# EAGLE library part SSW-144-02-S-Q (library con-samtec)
THROUGH-HOLE .025" SQ POST SOCKET Source: Samtec SSW.pdf
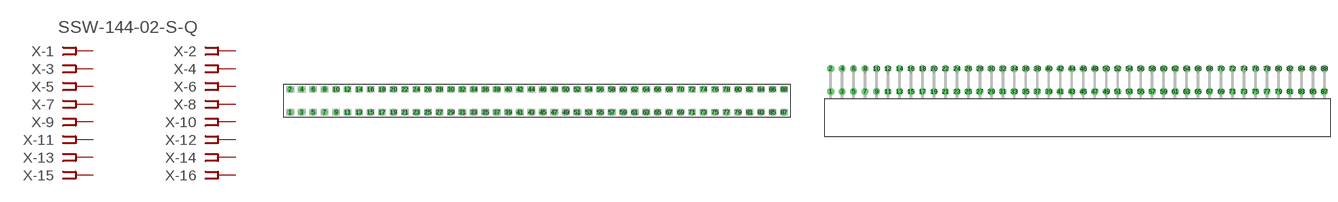
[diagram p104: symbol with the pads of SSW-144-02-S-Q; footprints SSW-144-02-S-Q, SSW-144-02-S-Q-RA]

Designator prefix X; gates -1=FPINV -2=FPIN -3=FPIN -4=FPIN -5=FPIN -6=FPIN -7=FPIN -8=FPIN -9=FPIN -10=FPIN -11=FPIN -12=FPIN -13=FPIN -14=FPIN -15=FPIN -16=FPIN -17=FPIN -18=FPIN -19=FPIN -20=FPIN -21=FPIN -22=FPIN -23=FPIN -24=FPIN -25=FPIN -26=FPIN -27=FPIN -28=FPIN -29=FPIN -30=FPIN -31=FPIN -32=FPIN -33=FPIN -34=FPIN -35=FPIN -36=FPIN -37=FPIN -38=FPIN -39=FPIN -40=FPIN -41=FPIN -42=FPIN -43=FPIN -44=FPIN -45=FPIN -46=FPIN -47=FPIN -48=FPIN -49=FPIN -50=FPIN -51=FPIN -52=FPIN -53=FPIN -54=FPIN -55=FPIN -56=FPIN -57=FPIN -58=FPIN -59=FPIN -60=FPIN -61=FPIN -62=FPIN -63=FPIN -64=FPIN -65=FPIN -66=FPIN -67=FPIN -68=FPIN -69=FPIN -70=FPIN -71=FPIN -72=FPIN -73=FPIN -74=FPIN -75=FPIN -76=FPIN -77=FPIN -78=FPIN -79=FPIN -80=FPIN -81=FPIN -82=FPIN -83=FPIN -84=FPIN -85=FPIN -86=FPIN -87=FPIN -88=FPIN

## SSW-144-02-S-Q (OC_FARNELL: unknown; OC_NEWARK: unknown)  [SSW-144-02-S-Q]
1  -1:1  pas
2  -2:1  pas
3  -3:1  pas
4  -4:1  pas
5  -5:1  pas
6  -6:1  pas
7  -7:1  pas
8  -8:1  pas
9  -9:1  pas
10  -10:1  pas
11  -11:1  pas
12  -12:1  pas
13  -13:1  pas
14  -14:1  pas
15  -15:1  pas
16  -16:1  pas
17  -17:1  pas
18  -18:1  pas
19  -19:1  pas
20  -20:1  pas
21  -21:1  pas
22  -22:1  pas
23  -23:1  pas
24  -24:1  pas
25  -25:1  pas
26  -26:1  pas
27  -27:1  pas
28  -28:1  pas
29  -29:1  pas
30  -30:1  pas
31  -31:1  pas
32  -32:1  pas
33  -33:1  pas
34  -34:1  pas
35  -35:1  pas
36  -36:1  pas
37  -37:1  pas
38  -38:1  pas
39  -39:1  pas
40  -40:1  pas
41  -41:1  pas
42  -42:1  pas
43  -43:1  pas
44  -44:1  pas
45  -45:1  pas
46  -46:1  pas
47  -47:1  pas
48  -48:1  pas
49  -49:1  pas
50  -50:1  pas
51  -51:1  pas
52  -52:1  pas
53  -53:1  pas
54  -54:1  pas
55  -55:1  pas
56  -56:1  pas
57  -57:1  pas
58  -58:1  pas
59  -59:1  pas
60  -60:1  pas
61  -61:1  pas
62  -62:1  pas
63  -63:1  pas
64  -64:1  pas
65  -65:1  pas
66  -66:1  pas
67  -67:1  pas
68  -68:1  pas
69  -69:1  pas
70  -70:1  pas
71  -71:1  pas
72  -72:1  pas
73  -73:1  pas
74  -74:1  pas
75  -75:1  pas
76  -76:1  pas
77  -77:1  pas
78  -78:1  pas
79  -79:1  pas
80  -80:1  pas
81  -81:1  pas
82  -82:1  pas
83  -83:1  pas
84  -84:1  pas
85  -85:1  pas
86  -86:1  pas
87  -87:1  pas
88  -88:1  pas

## SSW-144-02-S-QRA (OC_FARNELL: unknown; OC_NEWARK: unknown)  [SSW-144-02-S-Q-RA]
Pads as for SSW-144-02-S-Q

## Footprint SSW-144-02-S-Q (pad centres in mm)
THROUGH-HOLE .025" SQ POST SOCKET Source: Samtec SSW.pdf
drill 1 pad 1.5 octagon: 1 -54.61,-2.54; 2 -54.61,2.54; 3 -52.07,-2.54; 4 -52.07,2.54; 5 -49.53,-2.54; 6 -49.53,2.54; 7 -46.99,-2.54; 8 -46.99,2.54; 9 -44.45,-2.54; 10 -44.45,2.54; 11 -41.91,-2.54; 12 -41.91,2.54; 13 -39.37,-2.54; 14 -39.37,2.54; 15 -36.83,-2.54; 16 -36.83,2.54; 17 -34.29,-2.54; 18 -34.29,2.54; 19 -31.75,-2.54; 20 -31.75,2.54; 21 -29.21,-2.54; 22 -29.21,2.54; 23 -26.67,-2.54; 24 -26.67,2.54; 25 -24.13,-2.54; 26 -24.13,2.54; 27 -21.59,-2.54; 28 -21.59,2.54; 29 -19.05,-2.54; 30 -19.05,2.54; 31 -16.51,-2.54; 32 -16.51,2.54; 33 -13.97,-2.54; 34 -13.97,2.54; 35 -11.43,-2.54; 36 -11.43,2.54; 37 -8.89,-2.54; 38 -8.89,2.54; 39 -6.35,-2.54; 40 -6.35,2.54; 41 -3.81,-2.54; 42 -3.81,2.54; 43 -1.27,-2.54; 44 -1.27,2.54; 45 1.27,-2.54; 46 1.27,2.54; 47 3.81,-2.54; 48 3.81,2.54; 49 6.35,-2.54; 50 6.35,2.54; 51 8.89,-2.54; 52 8.89,2.54; 53 11.43,-2.54; 54 11.43,2.54; 55 13.97,-2.54; 56 13.97,2.54; 57 16.51,-2.54; 58 16.51,2.54; 59 19.05,-2.54; 60 19.05,2.54; 61 21.59,-2.54; 62 21.59,2.54; 63 24.13,-2.54; 64 24.13,2.54; 65 26.67,-2.54; 66 26.67,2.54; 67 29.21,-2.54; 68 29.21,2.54; 69 31.75,-2.54; 70 31.75,2.54; 71 34.29,-2.54; 72 34.29,2.54; 73 36.83,-2.54; 74 36.83,2.54; 75 39.37,-2.54; 76 39.37,2.54; 77 41.91,-2.54; 78 41.91,2.54; 79 44.45,-2.54; 80 44.45,2.54; 81 46.99,-2.54; 82 46.99,2.54; 83 49.53,-2.54; 84 49.53,2.54; 85 52.07,-2.54; 86 52.07,2.54; 87 54.61,-2.54; 88 54.61,2.54

## Footprint SSW-144-02-S-Q-RA (pad centres in mm)
THROUGH-HOLE .025" SQ POST SOCKET Source: Samtec SSW.pdf
drill 1 pad 1.5 octagon: 1 -54.61,1.524; 2 -54.61,6.604; 3 -52.07,1.524; 4 -52.07,6.604; 5 -49.53,1.524; 6 -49.53,6.604; 7 -46.99,1.524; 8 -46.99,6.604; 9 -44.45,1.524; 10 -44.45,6.604; 11 -41.91,1.524; 12 -41.91,6.604; 13 -39.37,1.524; 14 -39.37,6.604; 15 -36.83,1.524; 16 -36.83,6.604; 17 -34.29,1.524; 18 -34.29,6.604; 19 -31.75,1.524; 20 -31.75,6.604; 21 -29.21,1.524; 22 -29.21,6.604; 23 -26.67,1.524; 24 -26.67,6.604; 25 -24.13,1.524; 26 -24.13,6.604; 27 -21.59,1.524; 28 -21.59,6.604; 29 -19.05,1.524; 30 -19.05,6.604; 31 -16.51,1.524; 32 -16.51,6.604; 33 -13.97,1.524; 34 -13.97,6.604; 35 -11.43,1.524; 36 -11.43,6.604; 37 -8.89,1.524; 38 -8.89,6.604; 39 -6.35,1.524; 40 -6.35,6.604; 41 -3.81,1.524; 42 -3.81,6.604; 43 -1.27,1.524; 44 -1.27,6.604; 45 1.27,1.524; 46 1.27,6.604; 47 3.81,1.524; 48 3.81,6.604; 49 6.35,1.524; 50 6.35,6.604; 51 8.89,1.524; 52 8.89,6.604; 53 11.43,1.524; 54 11.43,6.604; 55 13.97,1.524; 56 13.97,6.604; 57 16.51,1.524; 58 16.51,6.604; 59 19.05,1.524; 60 19.05,6.604; 61 21.59,1.524; 62 21.59,6.604; 63 24.13,1.524; 64 24.13,6.604; 65 26.67,1.524; 66 26.67,6.604; 67 29.21,1.524; 68 29.21,6.604; 69 31.75,1.524; 70 31.75,6.604; 71 34.29,1.524; 72 34.29,6.604; 73 36.83,1.524; 74 36.83,6.604; 75 39.37,1.524; 76 39.37,6.604; 77 41.91,1.524; 78 41.91,6.604; 79 44.45,1.524; 80 44.45,6.604; 81 46.99,1.524; 82 46.99,6.604; 83 49.53,1.524; 84 49.53,6.604; 85 52.07,1.524; 86 52.07,6.604; 87 54.61,1.524; 88 54.61,6.604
